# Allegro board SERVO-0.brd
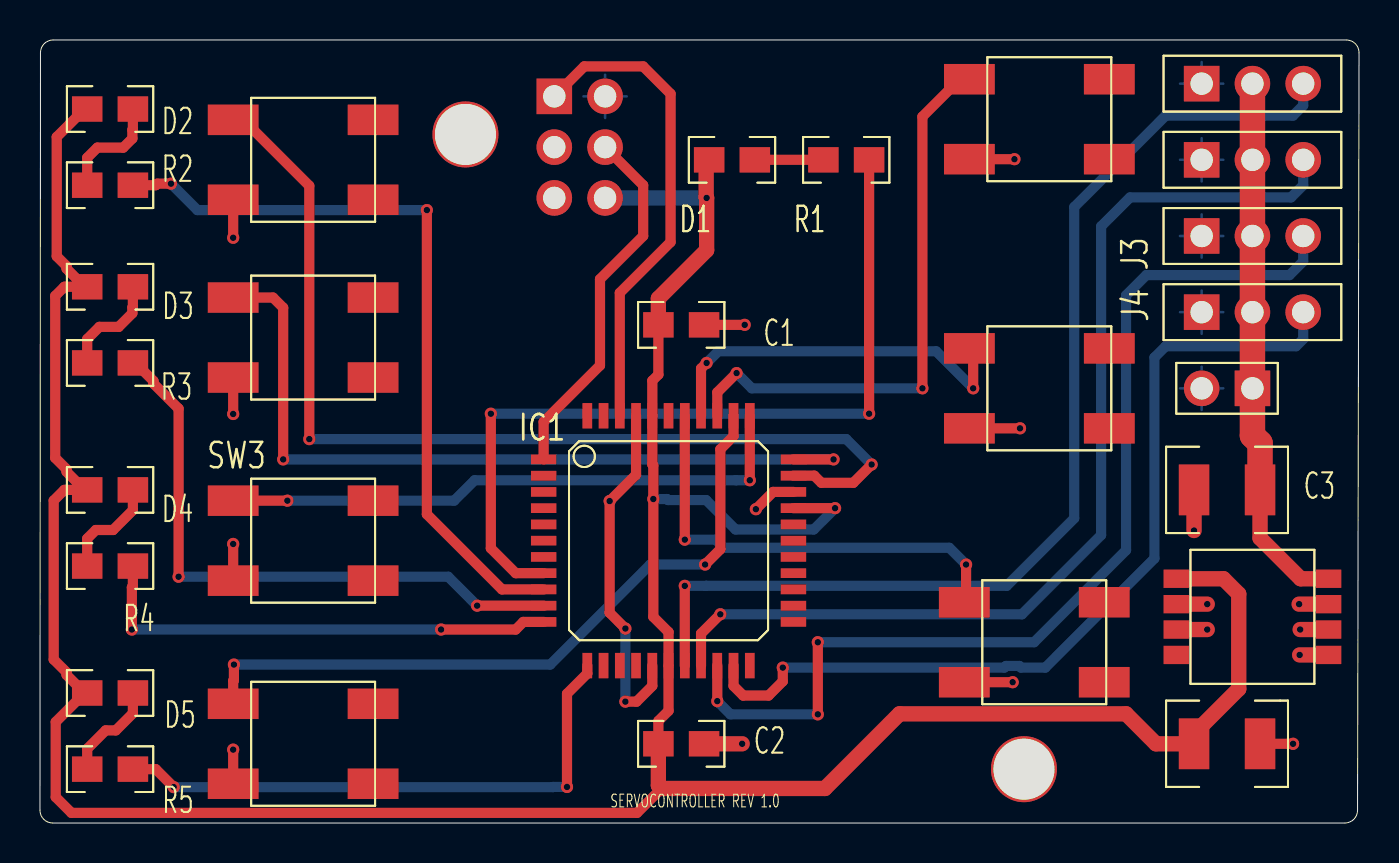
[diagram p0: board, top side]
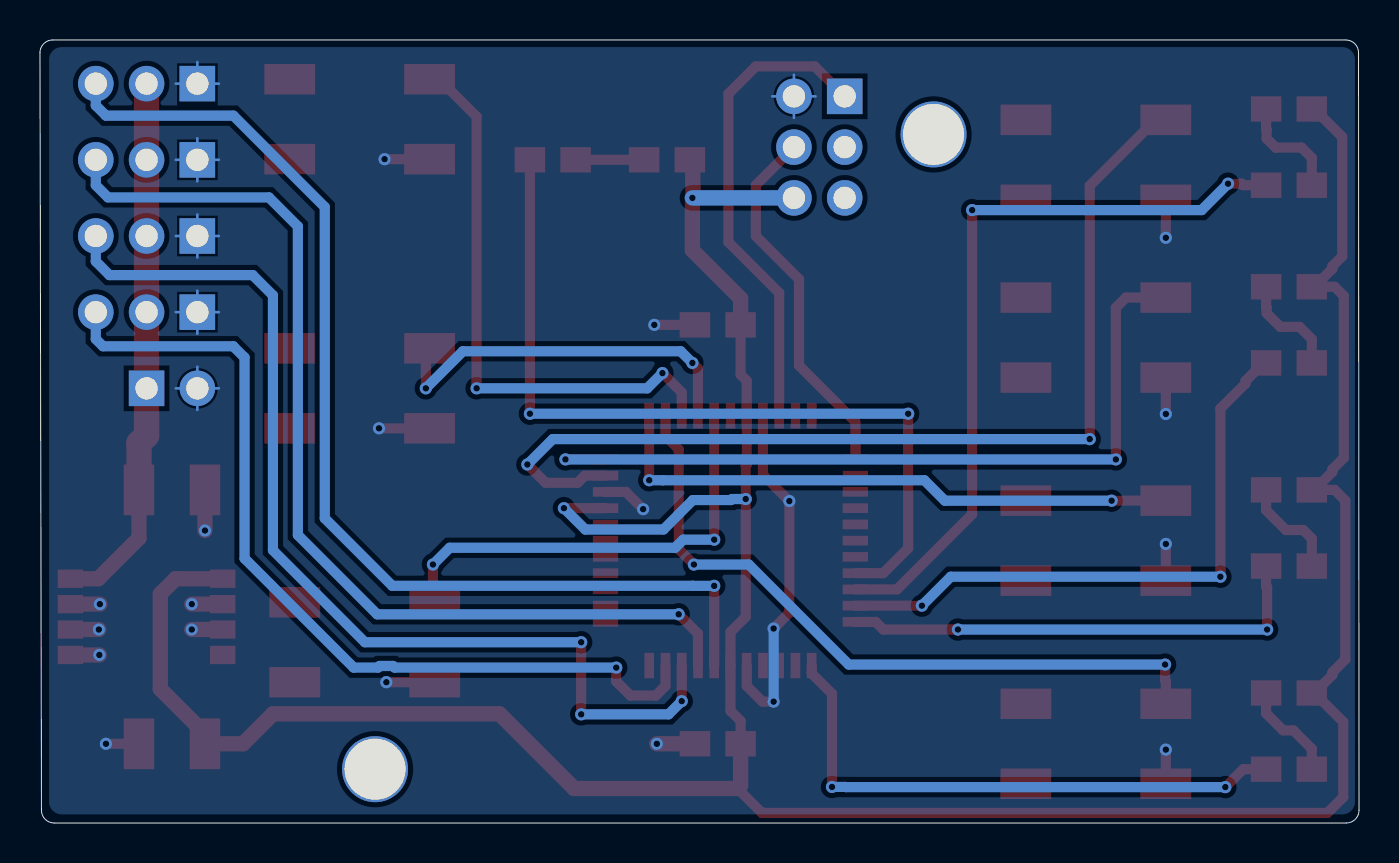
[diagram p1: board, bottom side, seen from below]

Outline 65.99 x 39.17 mm; copper layers: TOP, BOTTOM. Coordinates in mm from the lower left corner of the outline.
Outline path: 0,0.64 0.02,38.53 ; 0,0.64 0.02,38.53 ; 0,0.64 arc(0.19,0.19) 0.63,0 ; 0,0.64 arc(0.19,0.19) 0.63,0 ; 0.02,38.53 arc(0.21,38.98) 0.66,39.17 ; 0.02,38.53 arc(0.21,38.98) 0.66,39.17 ; 0.66,39.17 65.35,39.17 ; 0.66,39.17 65.35,39.17 ; 0.63,0 65.28,0 ; 0.63,0 65.28,0 ; 65.28,0 arc(65.73,0.19) 65.91,0.63 ; 65.28,0 arc(65.73,0.19) 65.91,0.63 ; 65.35,39.17 arc(65.8,38.98) 65.99,38.53 ; 65.35,39.17 arc(65.8,38.98) 65.99,38.53 ; 65.99,38.53 65.91,0.63 ; 65.99,38.53 65.91,0.63

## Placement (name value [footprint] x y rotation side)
C1  100nF  [0805RF_WV_12D]  32.08 24.92 0 top
C2  0.1uF  [0805RF_WV_12D]  32.08 3.96 0 top
C3  10uF 25V  [1210]  59.38 16.66 180 top
C4  10uF 10V  [1210]  59.38 3.96 0 top
D1  Led verde  [0805LED]  34.62 33.17 0 top
D2  Led rosso  [0805LED]  3.5 35.71 0 top
D3  Led rosso  [0805LED]  3.5 26.82 0 top
D4  Led rosso  [0805LED]  3.5 16.66 0 top
D5  Led rosso  [0805LED]  3.5 6.5 0 top
IC1  MC9S08GT16ACFBE  [PQFP44]  31.44 14.12 0 top
IC2  78LE33 SOIC8  [SOIC8W]  60.65 10.31 0 top
J1  HEADER 3  [JUMPER3]  60.65 36.98 90 top
J2  HEADER 3  [JUMPER3]  60.65 33.17 90 top
J3  HEADER 3  [JUMPER3]  60.65 29.36 90 top
J4  HEADER 3  [JUMPER3]  60.65 25.55 90 top
JP1  STRIP 3X2  [JUMPER3X2]  25.73 31.27 0 top
JP2  MORS. 5.08  [JUMPER2]  60.65 21.74 180 top
NOREF  -  [unnamed]  -75.24 -18.9 0 top
NOREF#2  -  [unnamed]  -47.3 -50.65 0 top
R1  1K  [0805RF_WV_12D]  40.33 33.17 0 top
R2  1K  [0805RF_WV_12D]  3.5 31.9 0 top
R3  1K  [0805RF_WV_12D]  3.5 23.01 0 top
R4  1K  [0805RF_WV_12D]  3.5 12.85 0 top
R5  1K  [0805RF_WV_12D]  3.5 2.69 0 top
SW1  SW PUSHBUTTON  [SW_BUTTON_SMD_CK]  13.66 33.17 0 top
SW2  SW PUSHBUTTON  [SW_BUTTON_SMD_CK]  13.66 24.28 0 top
SW3  SW PUSHBUTTON  [SW_BUTTON_SMD_CK]  13.66 14.12 0 top
SW4  SW PUSHBUTTON  [SW_BUTTON_SMD_CK]  13.66 3.96 0 top
SW5  SW PUSHBUTTON  [SW_BUTTON_SMD_CK]  50.49 35.2 0 top
SW6  SW PUSHBUTTON  [SW_BUTTON_SMD_CK]  50.49 21.74 0 top
SW7  SW PUSHBUTTON  [SW_BUTTON_SMD_CK]  50.24 9.04 0 top

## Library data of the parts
C1 = CAP_NP_1206
C2 = CAP_NP_0603
C3 C4 = CAP_POL_P100
D1-D5 = LED
IC1 = MC9S08GB60
IC2 = LEXX_0
J1-J4 = HEADER 3
JP1 = HEADER 3X2_0
JP2 = HEADER 2_0
R1-R5 = RES1206
SW1-SW7 = SW PUSHBUTTON_3

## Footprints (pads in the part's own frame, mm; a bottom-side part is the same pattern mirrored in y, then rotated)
0805LED
  rect 1.524x1.27 smd: 1(-1.143,0) 2(1.143,0)
0805RF_WV_12D
  rect 1.524x1.27 smd: 1(-1.143,0) 2(1.143,0)
1210
  rect 1.524x2.54 smd: 1(-1.651,0) 2(1.651,0)
JUMPER2
  rect 1.778x1.778 hole 1.118: 1(0,0)
  round 1.778 hole 1.118: 2(2.54,0)
JUMPER3
  rect 1.778x1.778 hole 1.118: 1(0,2.54)
  round 1.778 hole 1.118: 2(0,0) 3(0,-2.54)
JUMPER3X2
  rect 1.778x1.778 hole 1.118: 1(0,5.08)
  round 1.778 hole 1.118: 2(2.54,5.08) 3(0,2.54) 4(2.54,2.54) 5(0,0) 6(2.54,0)
PQFP44
  rect 1.27x0.483 smd: 1(-6.248,4.064) 2(-6.248,3.251) 3(-6.248,2.438) 4(-6.248,1.626) 5(-6.248,0.813) 6(-6.248,0) 7(-6.248,-0.813) 8(-6.248,-1.626) 9(-6.248,-2.438) 10(-6.248,-3.251) 11(-6.248,-4.064) 23(6.248,-4.064) 24(6.248,-3.251) 25(6.248,-2.438) 26(6.248,-1.626) 27(6.248,-0.813) 28(6.248,0) 29(6.248,0.813) 30(6.248,1.626) 31(6.248,2.438) 32(6.248,3.251) 33(6.248,4.064)
  rect 0.483x1.27 smd: 12(-4.064,-6.248) 13(-3.251,-6.248) 14(-2.438,-6.248) 15(-1.626,-6.248) 16(-0.813,-6.248) 17(0,-6.248) 18(0.813,-6.248) 19(1.626,-6.248) 20(2.438,-6.248) 21(3.251,-6.248) 22(4.064,-6.248) 34(4.064,6.248) 35(3.251,6.248) 36(2.438,6.248) 37(1.626,6.248) 38(0.813,6.248) 39(0,6.248) 40(-0.813,6.248) 41(-1.626,6.248) 42(-2.438,6.248) 43(-3.251,6.248) 44(-4.064,6.248)
SOIC8W
  rect 1.27x0.914 smd: 1(-3.81,1.905) 2(-3.81,0.635) 3(-3.81,-0.635) 4(-3.81,-1.905) 5(3.81,-1.905) 6(3.81,-0.635) 7(3.81,0.635) 8(3.81,1.905)
SW_BUTTON_SMD_CK
  rect 2.54x1.524 smd: 1(-4,2) 2(-4,-2) 3(3,-2) 4(3,2)
unnamed
  round 3.302 hole 3.048: (96.52,53.34)

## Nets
5V: C3.1 IC2.8(VIN) J1.2 J2.2 J3.2 J4.2 JP2.1
+3V3: C1.1 C2.1 C4.1 D1.1(ANODE) D2.1(ANODE) D3.1(ANODE) D4.1(ANODE) D5.1(ANODE) IC1.17(VDD) IC1.30(VREFH) IC1.40(VDDAD) IC2.1(VOUT) JP1.6
GND_POWER: C1.2 C2.2 C3.2 C4.2 IC1.16(VSS) IC1.31(VREFL) IC1.41(VSSAD) IC2.2(GND1) IC2.3(GND2) IC2.5(INH) IC2.6(GND3) IC2.7(GND4) J1.1 J2.1 J3.1 J4.1 JP1.2 JP2.2 SW1.2 SW2.2 SW3.2 SW4.2 SW5.2 SW6.2 SW7.2
LED_0: IC1.9(PTE0/TXD1) R2.2
LED_1: IC1.10(PTE1/RXD2) R3.2
LED_2: IC1.11(IRQ) R4.2
LED_3: IC1.12(PTE2/S\S\) R5.2
PWM_0: IC1.18(PTD0/TPM1CH0) J1.3
PWM_1: IC1.19(PTD1/TPM1CH1) J2.3
PWM_2: IC1.20(PTD2/TPM1CH2) J3.3
PWM_3: IC1.21(PTD3/TPM1CH3) J4.3
RESET: IC1.1(R\E\S\E\T\) JP1.4
RUN: IC1.8(PCT6) R1.2
N594673: IC1.42(PTG0/BKGD/MS) JP1.1
N2600003: IC1.32(PTA0/KBIP0) SW1.1
N2600007: IC1.33(PTA1/KBIP1) SW2.1
N2600019: IC1.34(PTA2/KBIP2) SW3.1
N2600031: IC1.35(PTA3/KBIP3) SW4.1
N2600043: IC1.36(PTA4/KBIP4) SW5.1
N2600055: IC1.37(PTA5/KBIP5) SW6.1
N2600067: IC1.38(PTA6/KBIP6) SW7.1
N5983350: D1.2(CATHODE) R1.1
N25987810: D2.2(CATHODE) R2.1
N25989410: D3.2(CATHODE) R3.1
N25991270: D4.2(CATHODE) R4.1
N25991710: D5.2(CATHODE) R5.1

Pads without a net: IC1 2 3 4 5 6 7 13 14 15 22 23 24 25 26 27 28 29 39 43 44; IC2 4; JP1 3 5; SW1 3 4; SW2 3 4; SW3 3 4; SW4 3 4; SW5 3 4; SW6 3 4; SW7 3 4

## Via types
v1: diameter 0.61, hole 0.33, TOP to BOTTOM, 53 vias

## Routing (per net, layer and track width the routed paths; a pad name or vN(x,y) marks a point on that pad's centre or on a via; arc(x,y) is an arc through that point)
5V: length 27.2
  TOP w0.762: IC2.8 63.07,12.22 61.04,14.25 C3.1
  TOP w1.27: C3.1 61.04,19 60.65,19.38 JP2.1 J4.2 J3.2 J2.2 J1.2
+3V3: length 163
  TOP w0.508: D4.1 2.23,16.66 ; 2.23,16.66 1.33,17.57 1.33,17.69 0.76,18.26 0.76,26.37 1.22,26.82 2.23,26.82 ; 2.23,16.66 1.22,16.66 0.69,16.13 0.69,8.18 1.33,7.53 1.33,7.41 2.23,6.5 ; 31.09,1.73 29.87,0.51 1.57,0.51 0.79,1.3 0.79,5.05 2.23,6.5 ; D3.1 2.23,26.82 ; 2.23,26.82 1.33,27.73 1.33,27.85 0.84,28.35 0.84,34.32 2.23,35.71 D2.1 ; 2.23,6.5 D5.1 ; C1.1 30.94,22.43 30.63,22.12 IC1.40 30.63,17.93 30.68,17.88 v1(30.68,16.21) 30.68,10.31 31.44,9.55 IC1.17 31.44,5.61 30.94,5.11 C2.1 30.81,3.96 ; IC1.30 v1(39.78,15.75)
  TOP w0.762: IC2.1 59.21,12.22 59.97,11.46 59.97,6.71 57.73,4.47 C4.1 55.83,3.96 54.33,5.46 43,5.46 39.27,1.73 31.09,1.73 30.94,1.88 C2.1 31.06,3.96 ; C1.1 30.94,26.24 33.35,28.65 v1(33.35,31.27) 33.33,31.29 33.33,33.02 D1.1
  BOTTOM w0.508: v1(39.78,15.75) 38.71,14.68 34.8,14.68 33.32,16.15 31.42,16.15 31.37,16.21 v1(30.68,16.21)
  BOTTOM w0.762: JP1.6 v1(33.35,31.27)
GND_POWER: length 74.6
  TOP w0.508: SW3.2 v1(9.66,13.96) ; v1(49.03,19.74) SW6.2 46.4,19.74 ; SW2.2 v1(9.66,20.46) ; IC1.41 29.82,17.42 v1(28.5,16.1) 28.5,10.52 v1(29.29,9.73) ; IC1.31 36.68,16.56 v1(35.81,15.7) ; SW7.2 v1(48.66,7.04) ; SW5.2 v1(48.75,33.2) ; v1(29.29,6.07) 29.84,6.07 30.63,6.86 IC1.16 ; SW4.2 v1(9.66,3.67) ; C1.2 v1(35.25,24.92) ; C4.2 v1(62.69,3.96) ; SW1.2 v1(9.66,29.27)
  TOP w0.762: IC2.6 v1(63.04,9.68) ; IC2.2 v1(58.39,10.95) ; IC2.7 v1(62.99,10.95) ; 64.46,8.41 v1(63.02,8.41) ; C2.2 v1(35.13,3.96) ; C3.2 v1(57.73,14.63) ; IC2.3 v1(58.39,9.68)
  BOTTOM w0.127: JP1.2 29.35,36.35 ; JP1.2 28.27,37.43 ; JP1.2 27.19,36.35 ; JP1.2 28.27,35.27 ; JP2.2 59.19,21.74 ; JP2.2 58.11,20.66 ; JP2.2 57.03,21.74 ; JP2.2 58.11,22.82 ; J1.1 59.19,36.98 ; J1.1 57.03,36.98 ; J1.1 58.11,38.06 ; J4.1 59.19,25.55 ; J4.1 57.03,25.55 ; J4.1 58.11,26.63 ; J4.1 58.11,24.47 ; J3.1 59.19,29.36 ; J3.1 58.11,28.28 ; J3.1 58.11,30.44 ; J3.1 57.03,29.36 ; J2.1 59.19,33.17 ; J2.1 58.11,34.25 ; J2.1 58.11,32.09 ; J2.1 57.03,33.17
  BOTTOM w0.508: v1(29.29,9.73) v1(29.29,6.07)
LED_0: length 37.9
  TOP w0.508: v1(19.35,30.66) 19.35,15.44 23.11,11.68 IC1.9 ; v1(6.55,31.98) 5.87,31.98 5.79,31.9 4.65,31.9
  BOTTOM w0.508: v1(19.35,30.66) 7.87,30.66 v1(6.55,31.98)
LED_1: length 30.6
  TOP w0.508: 4.65,23.01 4.77,23.01 5.68,22.11 5.68,21.98 6.93,20.73 v1(6.93,12.32) ; v1(21.87,10.87) IC1.10
  BOTTOM w0.508: v1(21.87,10.87) 20.42,12.32 v1(6.93,12.32)
LED_2: length 24
  TOP w0.508: IC1.11 24.18,10.06 23.8,9.68 v1(20.07,9.68) ; 4.65,12.85 4.65,11.84 4.6,11.79 v1(4.6,9.68)
  BOTTOM w0.508: v1(20.07,9.68) v1(4.6,9.68)
LED_3: length 28.6
  TOP w0.508: 4.65,2.69 5.79,2.69 v1(6.69,1.8) ; IC1.12 27.38,7.48 26.36,6.46 v1(26.36,1.8)
  BOTTOM w0.508: v1(6.69,1.8) 25.67,1.8 25.68,1.8 v1(26.36,1.8)
PWM_0: length 55.1
  TOP w0.508: v1(32.26,11.86) IC1.18
  BOTTOM w0.508: v1(32.26,11.86) 33.32,11.86 33.33,11.86 48.36,11.86 51.74,15.24 51.74,30.81 56.31,35.38 62.69,35.38 63.19,35.89 J1.3
PWM_1: length 51.3
  TOP w0.508: IC1.19 33.07,9.47 v1(34.04,10.44)
  BOTTOM w0.508: v1(34.04,10.44) 49.12,10.44 53.09,14.4 53.09,29.85 54.53,31.29 62.59,31.29 63.19,31.9 J2.3
PWM_2: length 51.6
  TOP w0.508: v1(33.88,6.1) IC1.20 ; v1(38.91,5.44) v1(38.91,9.04)
  BOTTOM w0.508: v1(38.91,9.04) 49.73,9.04 54.33,13.64 54.33,26.39 55.35,27.41 62.51,27.41 63.19,28.09 J3.3 ; v1(38.91,5.44) 34.54,5.44 v1(33.88,6.1)
PWM_3: length 44.8
  TOP w0.508: IC1.21 34.7,6.86 35.18,6.38 36.45,6.38 37.16,7.09 v1(37.16,7.77)
  BOTTOM w0.508: v1(37.16,7.77) 48.24,7.77 48.32,7.86 49,7.86 49.08,7.77 50.29,7.77 55.75,13.23 55.75,23.28 56.32,23.85 62.84,23.85 63.19,24.21 J4.3
RESET: length 18.5
  TOP w0.508: 28.27,33.81 30.17,31.9 30.17,29.36 28.02,27.2 28.02,22.89 25.2,20.07 IC1.1
RUN: length 41.5
  TOP w0.508: v1(41.48,20.47) R1.2 ; IC1.8 23.8,12.5 22.55,13.74 v1(22.55,20.47)
  BOTTOM w0.508: v1(22.55,20.47) v1(41.48,20.47)
N594673: length 24.2
  TOP w0.508: JP1.1 27.23,37.85 30.17,37.85 31.55,36.47 31.55,29.06 29.01,26.52 IC1.42
N2600003: length 50.9
  TOP w0.508: IC1.32 38.73,17.37 39.09,17.02 40.69,17.02 v1(41.6,17.93) ; v1(13.47,19.2) 13.47,31.87 10.17,35.17 SW1.1
  BOTTOM w0.508: v1(41.6,17.93) 40.33,19.2 v1(13.47,19.2)
N2600007: length 39.8
  TOP w0.508: SW2.1 11.66,26.28 12.17,25.77 v1(12.17,18.19) ; v1(39.7,18.19) IC1.33
  BOTTOM w0.508: v1(39.7,18.19) v1(12.17,18.19)
N2600019: length 29.5
  TOP w0.508: v1(12.38,16.12) SW3.1 ; IC1.34 v1(35.51,17.14)
  BOTTOM w0.508: v1(35.51,17.14) 34.82,17.14 21.74,17.14 20.72,16.12 v1(12.38,16.12)
N2600031: length 35.7
  TOP w0.508: v1(9.7,7.92) 9.7,7.14 9.66,7.11 SW4.1 ; v1(33.27,12.93) 34.04,13.69 34.04,18.69 34.7,19.35 IC1.35
  BOTTOM w0.508: v1(33.27,12.93) 30.53,12.93 25.53,7.92 v1(9.7,7.92)
N2600043: length 28.7
  TOP w0.508: IC1.36 33.88,21.54 v1(34.85,22.5) ; 46.4,37.08 45.89,37.08 44.14,35.33 v1(44.14,21.74)
  BOTTOM w0.508: v1(34.85,22.5) 35.61,21.74 v1(44.14,21.74)
N2600055: length 19.2
  TOP w0.508: 46.4,23.74 46.68,23.46 v1(46.68,21.74) ; v1(33.35,23.01) 33.07,22.73 IC1.37
  BOTTOM w0.508: v1(33.35,23.01) 33.93,23.6 44.83,23.6 v1(46.68,21.74)
N2600067: length 22.7
  TOP w0.508: IC1.38 v1(32.26,14.17) ; v1(46.33,12.93) 46.33,11.11 46.4,11.04
  BOTTOM w0.508: v1(46.33,12.93) 45.49,13.77 34.21,13.77 33.81,14.17 v1(32.26,14.17)
N5983350: length 3.4
  TOP w0.508: D1.2 R1.1
N25987810: length 5.5
  TOP w0.508: 4.65,35.71 4.65,34.7 4.62,34.67 4.62,34.24 4.17,33.78 2.87,33.78 2.36,33.27 R2.1
N25989410: length 5.3
  TOP w0.508: R3.1 2.36,24.21 2.97,24.82 3.94,24.82 4.62,25.5 4.62,25.78 4.65,25.81 4.65,26.82
N25991270: length 5.4
  TOP w0.508: R4.1 2.36,14.22 2.79,14.66 3.66,14.66 4.65,15.65 4.65,16.66 4.52,16.66
N25991710: length 5.1
  TOP w0.508: R5.1 2.36,3.71 3.29,4.63 3.79,4.63 4.65,5.49 4.65,6.5

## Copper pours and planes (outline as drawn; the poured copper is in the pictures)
GND_POWER on BOTTOM: 0.2,38.18 0.39,38.63 0.84,38.81 64.9,38.81 65.35,38.63 65.53,38.18 65.53,1.07 65.35,0.62 64.9,0.43 0.84,0.43 0.39,0.62 0.2,1.07

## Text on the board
Ref Des/Silkscreen Top: SERVOCONTROLLER REV 1.0
NCLEGEND-1-2: FIGURE | SIZE | 13.0 | 44.0 | 120.0 | DRILL CHART: TOP to BOTTOM | ALL UNITS ARE IN MILS | PLATED | QTY | 53 | 20 | 2
